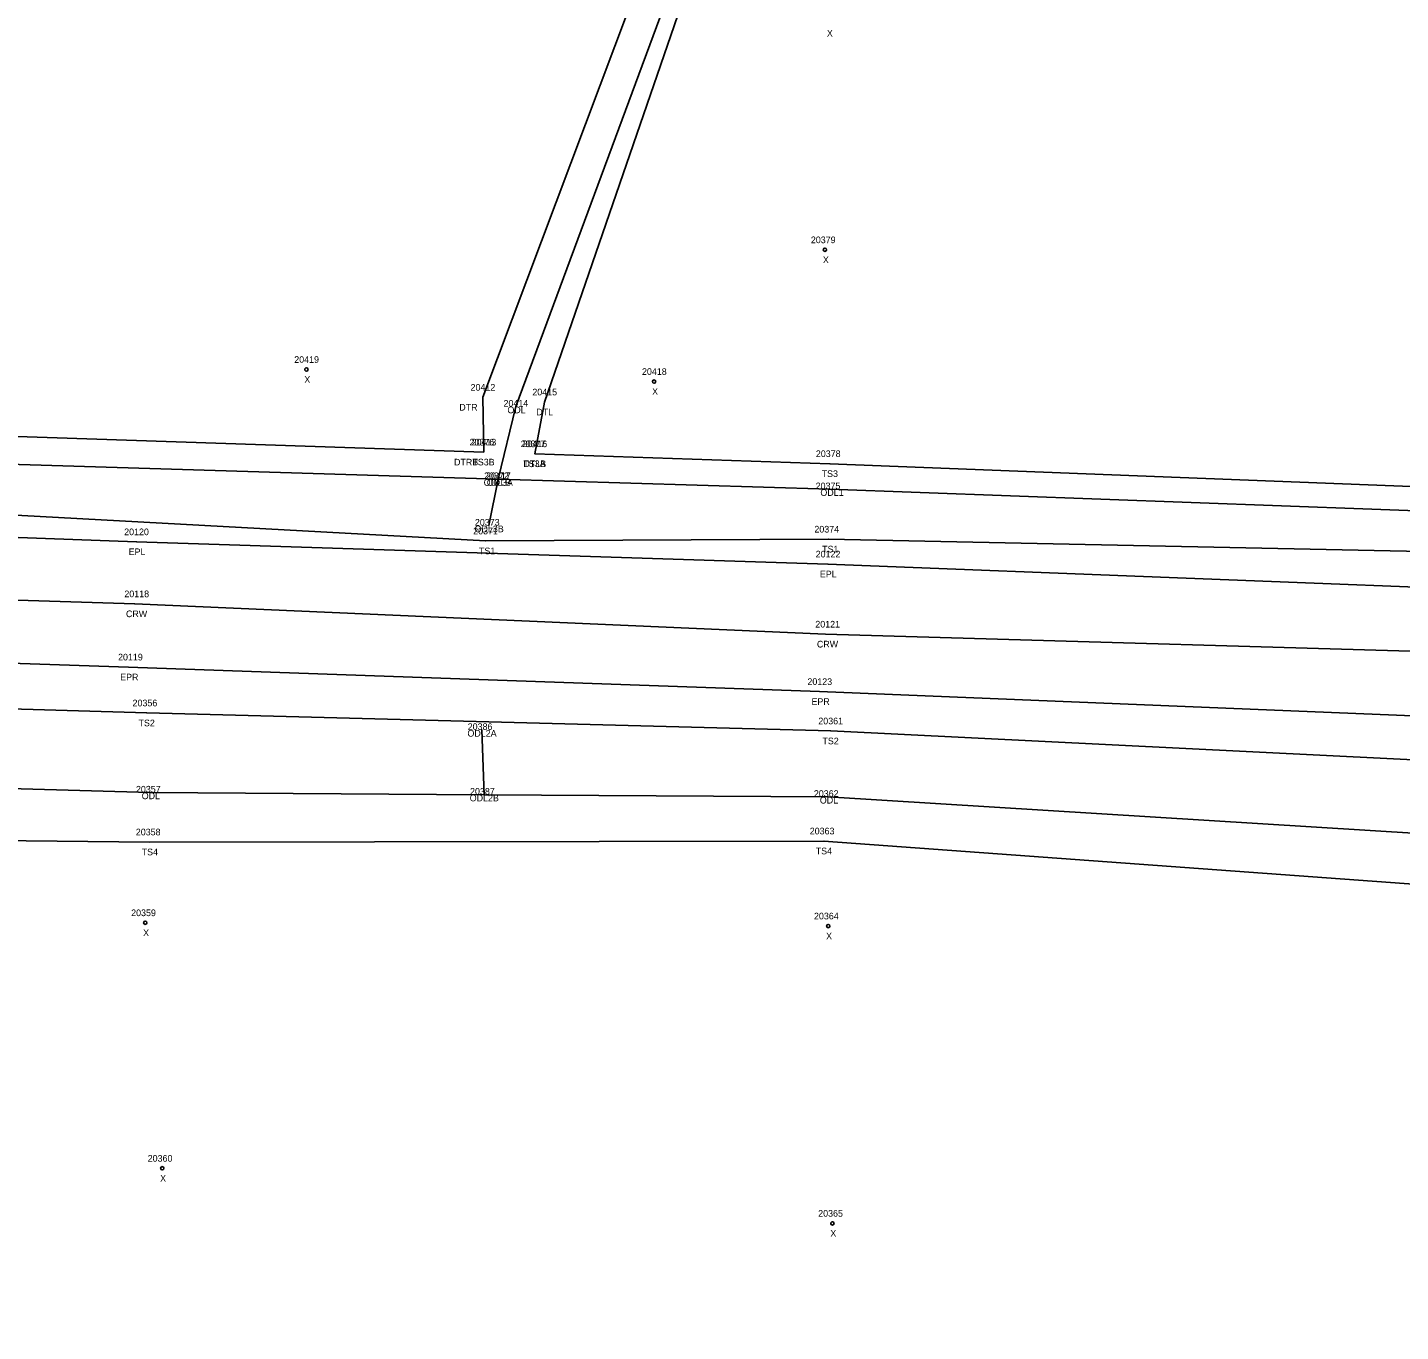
# Model space of a CAD drawing. Extents: x 1966740 to 1969291, y 1117378 to 1118461.
# Drawn here: x 1968302.4 to 1968508.9, y 1117814.5 to 1118010.6 of the extents above; entities that cross this region are included whole.
import ezdxf

# ---------------------------------------------------------------- set-up
doc = ezdxf.new("R2010")
doc.units = 0
for name, color, linetype in [('RD_DTM_BkLn1', 7, 'Continuous'), ('RD_DTM_BkLn2', 7, 'Continuous'), ('RD_EX_H2O', 7, 'Continuous'), ('RD_EX_H2O_txCode', 7, 'Continuous'), ('RD_EX_Road', 7, 'Continuous'), ('RD_EX_Road_txCode', 7, 'Continuous'), ('RD_SMD_Locator', 7, 'Continuous'), ('RD_SMD_Misc', 7, 'Continuous')]:
    doc.layers.add(name, color=color, linetype=linetype)

msp = doc.modelspace()

# ---------------------------------------------------------------- linework, layer by layer
at = {"layer": 'RD_DTM_BkLn1'}
msp.add_lwpolyline([(1967878.98, 1117895.46), (1967922.07, 1117909.4), (1967968.89, 1117921.38), (1968013.49, 1117926.44), (1968059.29, 1117929.05), (1968105.63, 1117929.86), (1968159.12, 1117928.97), (1968212.65, 1117927.25), (1968318.5, 1117923.95), (1968422.42, 1117919.39), (1968529.36, 1117916.3)], dxfattribs=at)
at = {"layer": 'RD_DTM_BkLn2'}
for points in [[(1968106.63, 1117967.98), (1968158.56, 1117954.16), (1968212.75, 1117952.09), (1968371.01, 1117946.77)], [(1968378.68, 1117946.52), (1968423.07, 1117945.03), (1968532.27, 1117940.77)], [(1967874.77, 1117908.42), (1967879.51, 1117916.91), (1967881.27, 1117924.39), (1967885.24, 1117929.22), (1967913.7, 1117935.63), (1967966.11, 1117937.12), (1968012.39, 1117940.75), (1968059.42, 1117941.87), (1968105.44, 1117943.27), (1968158.32, 1117942.95), (1968212.48, 1117942.1), (1968371.25, 1117933.41), (1968422.85, 1117933.68), (1968531.49, 1117931.42)], [(1967884.1, 1117882.92), (1967891.06, 1117879.24), (1967898.84, 1117879.11), (1967924.17, 1117888.04), (1967954.33, 1117900.3), (1967970.81, 1117903.15), (1968012.93, 1117910.83), (1968059.62, 1117915.05), (1968105.25, 1117916.2), (1968157.57, 1117912.09), (1968210.74, 1117910.77), (1968320.32, 1117907.54), (1968423.18, 1117904.83), (1968528.99, 1117899.6)], [(1968058.02, 1117883.74), (1968104.17, 1117887.52), (1968156.67, 1117888.05), (1968209.1, 1117889.3), (1968320.79, 1117888.13), (1968422.17, 1117888.28), (1968528.68, 1117880.51)]]:
    msp.add_lwpolyline(points, dxfattribs=at)
at = {"layer": 'RD_EX_H2O'}
for p, q in [((1968373.17, 1117942.71), (1968371.79, 1117935.72)), ((1968370.73, 1117904.98), (1968371.06, 1117895.25))]:
    msp.add_line(p, q, dxfattribs=at)
for points in [[(1968464.83, 1118211.88), (1968447.38, 1118161.72), (1968428.66, 1118112.3), (1968410.49, 1118060.76), (1968392.92, 1118013.68), (1968370.86, 1117955.02), (1968371.01, 1117946.77)], [(1968468.44, 1118210.37), (1968452.83, 1118159.99), (1968434.15, 1118109.1), (1968414.75, 1118059.53), (1968397.98, 1118013.47), (1968375.81, 1117953.62), (1968373.17, 1117942.71)], [(1968473.95, 1118208.63), (1968457.08, 1118158.03), (1968439.1, 1118107.96), (1968419.78, 1118057.77), (1968400.7, 1118013.97), (1968380.14, 1117954.31), (1968378.68, 1117946.52)], [(1968105.42, 1117949), (1968158.12, 1117948.98), (1968212.69, 1117947.6), (1968373.17, 1117942.71)], [(1968373.17, 1117942.71), (1968423.04, 1117941.19), (1968531.76, 1117937.18)], [(1967868.28, 1117817.14), (1967892.54, 1117814.5), (1967928.24, 1117834.22), (1967973.92, 1117854.29), (1967982.67, 1117861.15), (1968021.78, 1117883.3), (1968056.97, 1117897.44), (1968105.42, 1117898.77), (1968155.9, 1117899.84), (1968209.66, 1117898.76), (1968320.81, 1117895.57), (1968371.06, 1117895.25)], [(1968371.06, 1117895.25), (1968422.79, 1117894.92), (1968528.55, 1117888.35)]]:
    msp.add_lwpolyline(points, dxfattribs=at)
at = {"layer": 'RD_EX_Road'}
for points in [[(1967878.98, 1117895.46), (1967875.66, 1117903.48), (1967919.49, 1117917.47), (1967966.4, 1117928.95), (1968012.66, 1117935.42), (1968058.94, 1117938.37), (1968105.99, 1117939.39), (1968158.7, 1117938.56), (1968212.05, 1117937.21), (1968318.79, 1117933.28), (1968422.76, 1117929.93), (1968530.54, 1117925.7)], [(1967878.98, 1117895.46), (1967883.11, 1117885.63), (1967924.99, 1117899.59), (1967970.68, 1117910.78), (1968014.42, 1117916.56), (1968059.13, 1117919.49), (1968105.39, 1117920.31), (1968159.16, 1117919.37), (1968212.5, 1117917.97), (1968317.55, 1117914.44), (1968421.52, 1117910.75), (1968527.82, 1117906.41)]]:
    msp.add_lwpolyline(points, dxfattribs=at)
at = {"layer": 'RD_SMD_Locator'}
for centre, radius in [((1968422.32, 1117977.2), 0.25), ((1968344.33, 1117959.2), 0.25), ((1968396.63, 1117957.39), 0.25), ((1968370.86, 1117955.02), 0.001), ((1968375.81, 1117953.62), 0.001), ((1968380.14, 1117954.31), 0.001), ((1968371.01, 1117946.77), 0.001), ((1968371.01, 1117946.77), 0.001), ((1968378.68, 1117946.52), 0.001), ((1968378.68, 1117946.52), 0.001), ((1968423.07, 1117945.03), 0.001), ((1968373.17, 1117942.71), 0.001), ((1968373.17, 1117942.71), 0.001), ((1968423.04, 1117941.19), 0.001), ((1968371.79, 1117935.72), 0.001), ((1968318.79, 1117933.28), 0.001), ((1968371.25, 1117933.41), 0.001), ((1968422.85, 1117933.68), 0.001), ((1968422.76, 1117929.93), 0.001), ((1968318.5, 1117923.95), 0.001), ((1968422.42, 1117919.39), 0.001), ((1968317.55, 1117914.44), 0.001), ((1968421.52, 1117910.75), 0.001), ((1968320.32, 1117907.54), 0.001), ((1968370.73, 1117904.98), 0.001), ((1968423.18, 1117904.83), 0.001), ((1968320.81, 1117895.57), 0.001), ((1968371.06, 1117895.25), 0.001), ((1968422.79, 1117894.92), 0.001), ((1968320.79, 1117888.13), 0.001), ((1968422.17, 1117888.28), 0.001), ((1968320.08, 1117875.98), 0.25), ((1968422.81, 1117875.49), 0.25), ((1968322.64, 1117839.05), 0.25), ((1968423.45, 1117830.77), 0.25)]:
    msp.add_circle(centre, radius, dxfattribs=at)

# ---------------------------------------------------------------- texts
at = {"layer": 'RD_EX_H2O_txCode'}
for s, p in [('20412', (1968369.02, 1117956.02)), ('20415', (1968378.31, 1117955.31)), ('DTR', (1968367.32, 1117953.02)), ('20414', (1968373.97, 1117953.62)), ('ODL', (1968374.56, 1117952.62)), ('DTL', (1968378.9, 1117952.31)), ('20413', (1968369.17, 1117947.77)), ('20416', (1968376.82, 1117947.52)), ('DTRB', (1968366.53, 1117944.77)), ('DTLB', (1968376.96, 1117944.52)), ('20372', (1968371.05, 1117942.71)), ('20417', (1968371.34, 1117942.71)), ('ODL3A', (1968370.99, 1117941.71)), ('ODLB', (1968371.46, 1117941.71)), ('20375', (1968420.92, 1117941.19)), ('ODL1', (1968421.63, 1117940.19)), ('ODL3B', (1968369.62, 1117934.72)), ('20373', (1968369.67, 1117935.72)), ('20386', (1968368.59, 1117904.98)), ('ODL2A', (1968368.55, 1117903.98)), ('20357', (1968318.69, 1117895.57)), ('ODL', (1968319.56, 1117894.57)), ('20387', (1968368.94, 1117895.25)), ('20362', (1968420.65, 1117894.92)), ('ODL2B', (1968368.89, 1117894.25)), ('ODL', (1968421.55, 1117893.92))]:
    msp.add_text(s, height=1, dxfattribs=at).set_placement(p)
at = {"layer": 'RD_EX_Road_txCode'}
for s, p in [('20120', (1968316.92, 1117934.28)), ('EPL', (1968317.59, 1117931.28)), ('20122', (1968420.92, 1117930.93)), ('EPL', (1968421.55, 1117927.93)), ('20119', (1968316, 1117915.44)), ('EPR', (1968316.32, 1117912.44)), ('20123', (1968419.68, 1117911.75)), ('EPR', (1968420.29, 1117908.75))]:
    msp.add_text(s, height=1, dxfattribs=at).set_placement(p)
at = {"layer": 'RD_SMD_Misc'}
for s, p in [('X', (1968422.61, 1118009.27)), ('20379', (1968420.2, 1117978.2)), ('X', (1968422.01, 1117975.2)), ('20419', (1968342.5, 1117960.2)), ('X', (1968344.02, 1117957.2)), ('20418', (1968394.8, 1117958.39)), ('X', (1968396.32, 1117955.39)), ('20376', (1968368.86, 1117947.77)), ('20377', (1968376.56, 1117947.52)), ('TS3B', (1968369.29, 1117944.77)), ('TS3A', (1968376.95, 1117944.52)), ('20378', (1968420.95, 1117946.03)), ('TS3', (1968421.82, 1117943.03)), ('20371', (1968369.41, 1117934.41)), ('20374', (1968420.73, 1117934.68)), ('TS1', (1968421.89, 1117931.68)), ('TS1', (1968370.28, 1117931.41)), ('20118', (1968316.95, 1117924.95)), ('CRW', (1968317.19, 1117921.95)), ('20121', (1968420.87, 1117920.39)), ('CRW', (1968421.11, 1117917.39)), ('20356', (1968318.18, 1117908.54)), ('TS2', (1968319.08, 1117905.54)), ('20361', (1968421.32, 1117905.83)), ('TS2', (1968421.94, 1117902.83)), ('20358', (1968318.67, 1117889.13)), ('20363', (1968420.03, 1117889.28)), ('TS4', (1968420.93, 1117886.28)), ('TS4', (1968319.55, 1117886.13)), ('20359', (1968317.97, 1117876.98)), ('20364', (1968420.67, 1117876.49)), ('X', (1968319.77, 1117873.98)), ('X', (1968422.49, 1117873.49)), ('20360', (1968320.46, 1117840.05)), ('X', (1968322.33, 1117837.05)), ('20365', (1968421.3, 1117831.77)), ('X', (1968423.13, 1117828.77))]:
    msp.add_text(s, height=1, dxfattribs=at).set_placement(p)

doc.saveas('drawing.dxf')
